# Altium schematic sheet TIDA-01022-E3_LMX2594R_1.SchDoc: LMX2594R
size 431 x 279 mm; Date: Not shown in title block; ApprovedBy: Not shown in title block; CheckedBy: Not shown in title block; Author: Not shown in title block; CompanyName: Not shown in title block; DrawnBy: Avinash N; Engineer: Not shown in title block; Organization: Not shown in title block; Address1: Not shown in title block; Address2: Not shown in title block; Address3: Not shown in title block; Address4: Not shown in title block; DocumentNumber: 1; Revision: Use project parameter SCH_Rev; SheetNumber: 10; SheetTotal: 26; PageSetup: Record=PageOptions¦CenterHorizontal=True¦CenterVertical=True¦PrintScale=1.00¦XCorrection=1.00¦YCorrection=1.00¦PrintKind=0¦BorderSize=5000000¦LeftOffset=0¦BottomOffset=0¦Orientation=2¦PaperLength=1000¦PaperWidth=1000¦Scale=100¦PaperSource=15¦PrintQuality=600¦MediaType=1¦DitherType=10¦PaperKind=Letter¦PrintScaleMode=1
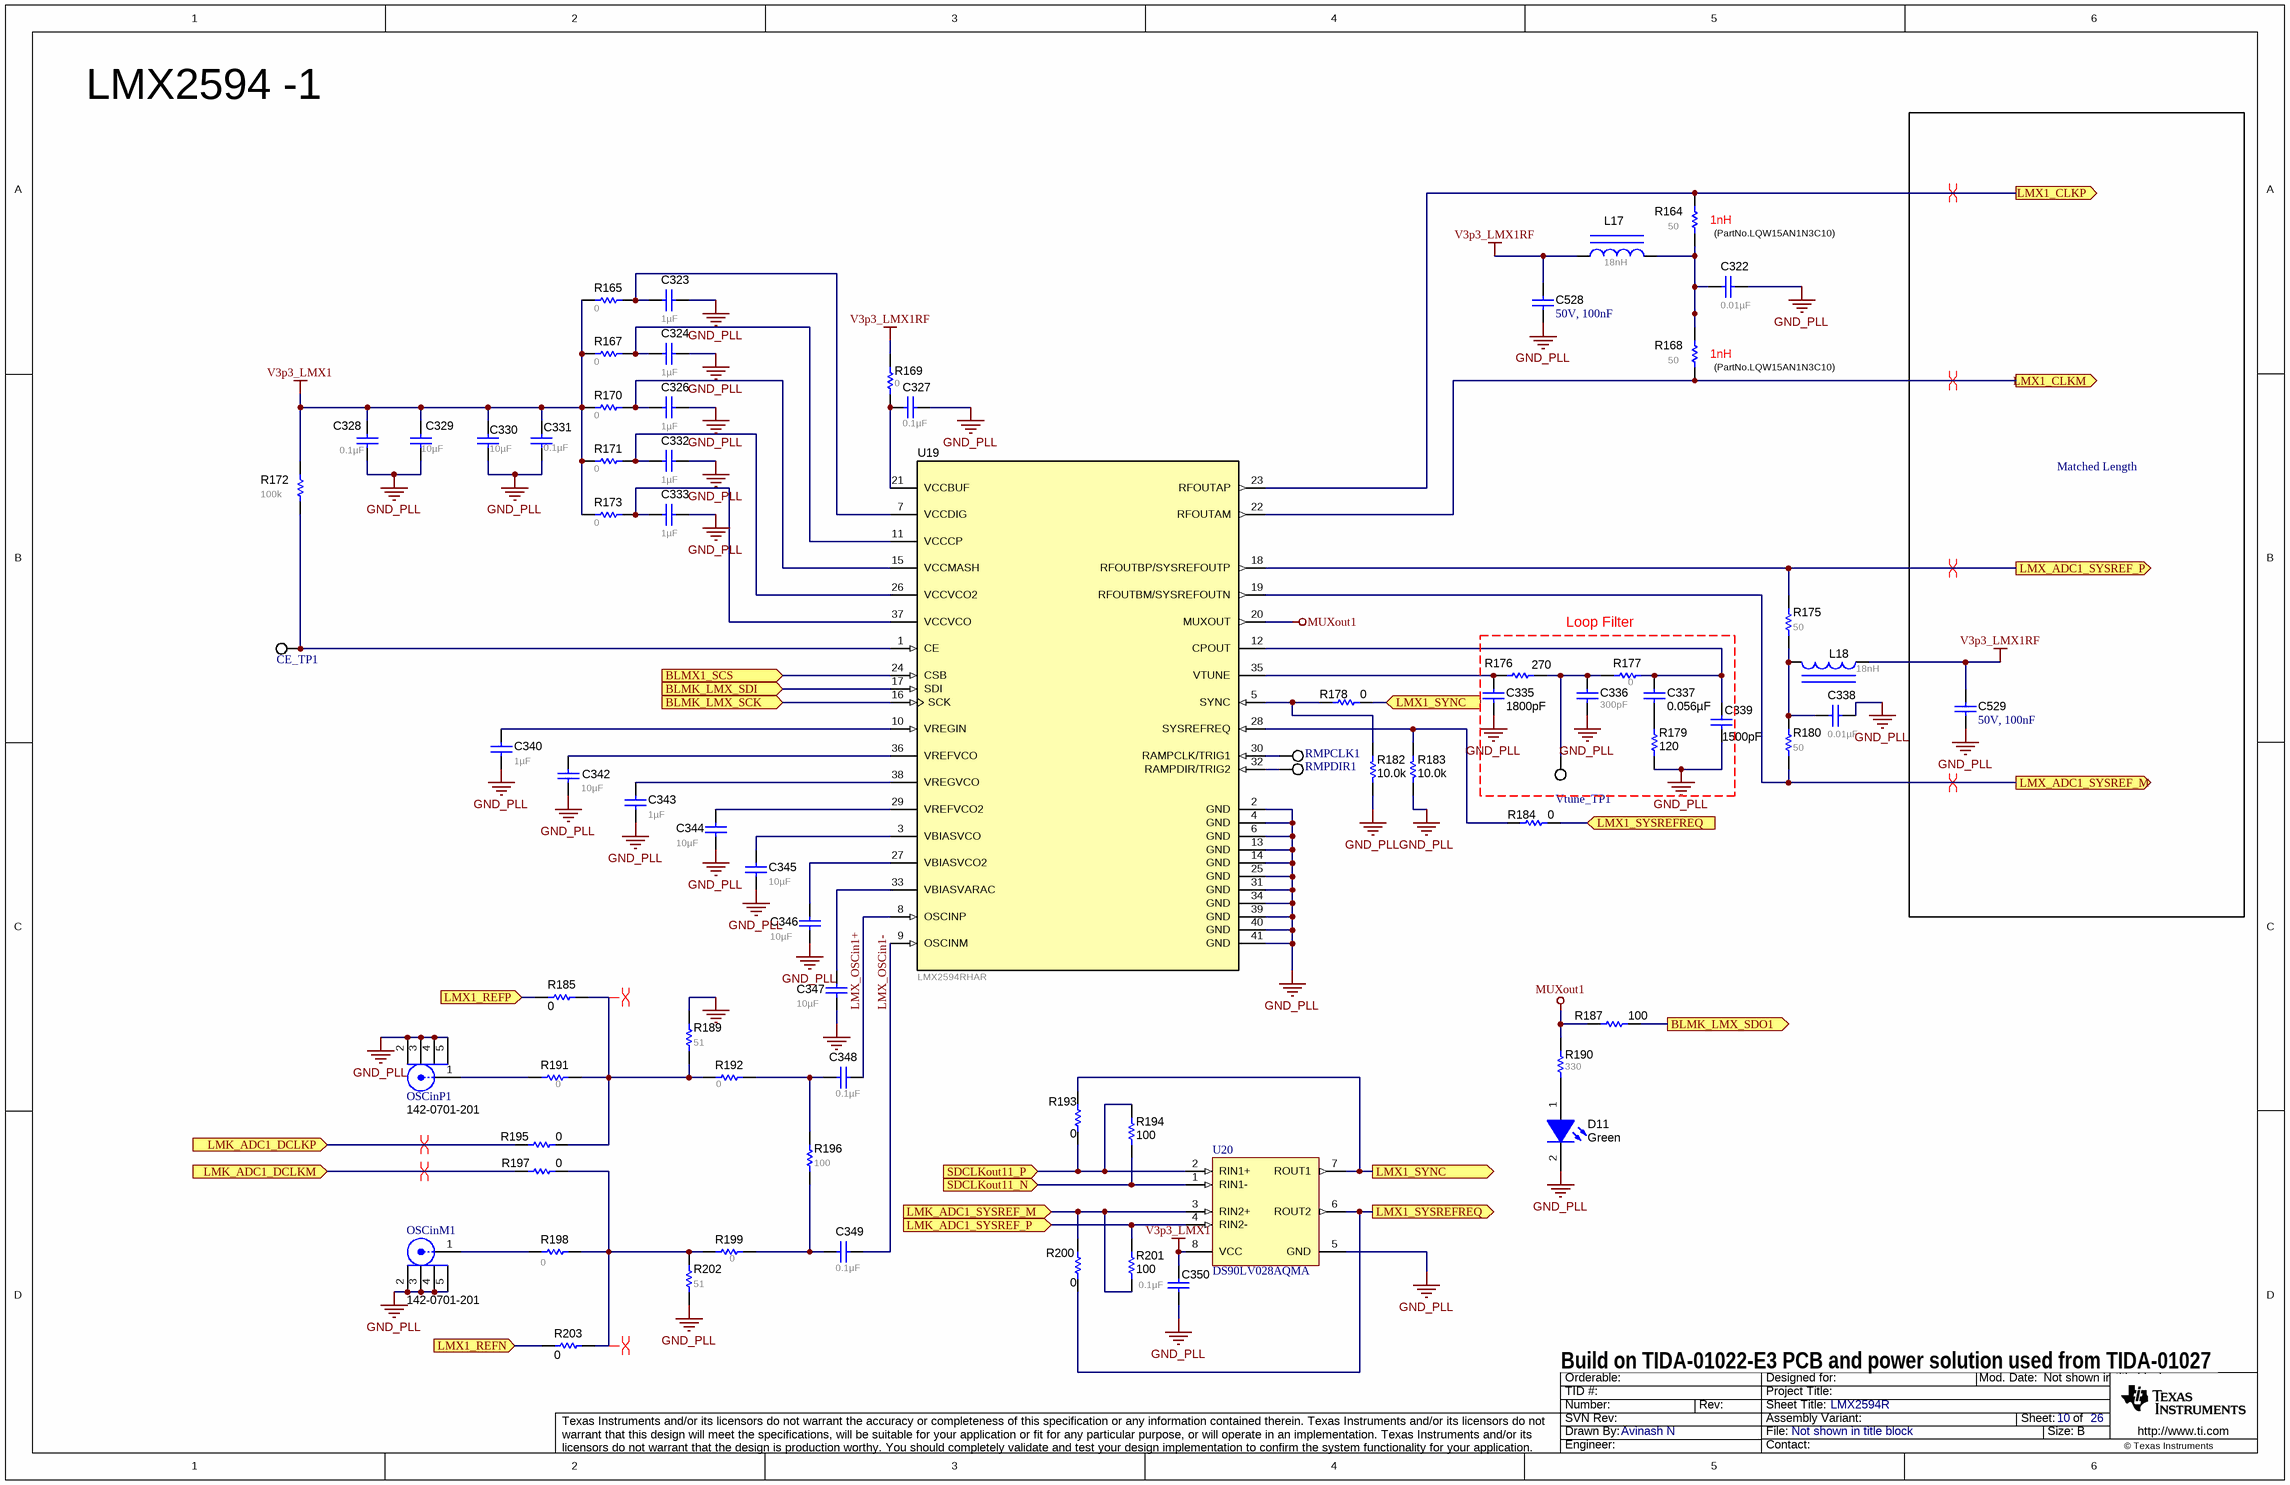
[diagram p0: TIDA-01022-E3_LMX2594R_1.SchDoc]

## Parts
C322  ValueDisplayed: 0.01µF  [0402_065]  (hidden comment: 520L103KT16T)
C323  ValueDisplayed: 1µF  [0603]  (hidden comment: C1608X7R1C105K080AC)
C324  ValueDisplayed: 1µF  [0603L]  (hidden comment: C1608X7R1C105K080AC)
C326  ValueDisplayed: 1µF  [0603L]  (hidden comment: C1608X7R1C105K080AC)
C327  ValueDisplayed: 0.1µF  [0603L]  (hidden comment: 0603YC104JAT2A)
C328  ValueDisplayed: 0.1µF  [0603]  (hidden comment: 0603YC104JAT2A)
C329  ValueDisplayed: 10µF  [0805]  (hidden comment: C0805C106K8PACTU)
C330  ValueDisplayed: 10µF  [0805]  (hidden comment: C0805C106K8PACTU)
C331  ValueDisplayed: 0.1µF  [0603]  (hidden comment: 0603YC104JAT2A)
C332  ValueDisplayed: 1µF  [0603]  (hidden comment: C1608X7R1C105K080AC)
C333  ValueDisplayed: 1µF  [0603]  (hidden comment: C1608X7R1C105K080AC)
C335  ValueDisplayed: 1800pF  [0603]  (hidden comment: GRM1885C1H182JA01D)
C336  ValueDisplayed: 300pF  [0603]  (hidden comment: GRM1885C2A301JA01D)
C337  ValueDisplayed: 0.056µF  [0603]  (hidden comment: C0603C563J4RACTU)
C338  ValueDisplayed: 0.01µF  [0402_065]  (hidden comment: 520L103KT16T)
C339  ValueDisplayed: 1500pF  [0603]  (hidden comment: 06031C152JAT2A)
C340  ValueDisplayed: 1µF  [0603]  (hidden comment: C1608X7R1C105K080AC)
C342  ValueDisplayed: 10µF  [0603]  (hidden comment: C1608X5R1A106M080AC)
C343  ValueDisplayed: 1µF  [0603]  (hidden comment: C1608X7R1C105K080AC)
C344  ValueDisplayed: 10µF  [0603]  (hidden comment: C1608X5R1A106M080AC)
C345  ValueDisplayed: 10µF  [0603]  (hidden comment: C1608X5R1A106M080AC)
C346  ValueDisplayed: 10µF  [0603]  (hidden comment: C1608X5R1A106M080AC)
C347  ValueDisplayed: 10µF  [0603]  (hidden comment: C1608X5R1A106M080AC)
C348  ValueDisplayed: 0.1µF  [0603L]  (hidden comment: 0603YC104JAT2A)
C349  ValueDisplayed: 0.1µF  [0603L]  (hidden comment: 0603YC104JAT2A)
C350  ValueDisplayed: 0.1µF  [0603]  (hidden comment: 0603YC104JAT2A)
C528  50V, 100nF  [0603_1.6x0.8x0.8mm_Reflow Soldering]
C529  50V, 100nF  [0603_1.6x0.8x0.8mm_Reflow Soldering]
CE_TP1  5002  [Keystone5002]  (value not drawn)
D11  value Green  [LTST-C191_Green]  (hidden comment: LTST-C191TGKT)
L17  ValueDisplayed: 18nH  [IND_LQG15H]  (hidden comment: LQG15HS18NJ02D)
L18  ValueDisplayed: 18nH  [IND_LQG15H]  (hidden comment: LQG15HS18NJ02D)
OSCinM1  142-0701-201  [Johnson_142-0701-20x]
OSCinP1  142-0701-201  [Johnson_142-0701-20x]
R164  ValueDisplayed: 50  [0402L]  (hidden comment: FC0402E50R0BST1)
R165  value 0  [0603]  (hidden comment: CRCW06030000Z0EA)
R167  value 0  [0603L]  (hidden comment: CRCW06030000Z0EA)
R168  ValueDisplayed: 50  [0402L]  (hidden comment: FC0402E50R0BST1)
R169  value 0  [0603L]  (hidden comment: CRCW06030000Z0EA)
R170  value 0  [0603L]  (hidden comment: CRCW06030000Z0EA)
R171  value 0  [0603]  (hidden comment: CRCW06030000Z0EA)
R172  ValueDisplayed: 100k  [0603]  (hidden comment: CRCW0603100KJNEA)
R173  value 0  [0603]  (hidden comment: CRCW06030000Z0EA)
R175  ValueDisplayed: 50  [0402L]  (hidden comment: FC0402E50R0BST1)
R176  ValueDisplayed: 270  [0603]  (hidden comment: RC0603JR-07270RL)
R177  ValueDisplayed: 0  [0603]  (hidden comment: CRCW06030000Z0EA)
R178  ValueDisplayed: 0  [0402]  (hidden comment: CRCW04020000Z0ED)
R179  ValueDisplayed: 120  [0603]  (hidden comment: RT0603DRE07120RL)
R180  ValueDisplayed: 50  [0402L]  (hidden comment: FC0402E50R0BST1)
R182  ValueDisplayed: 10.0k  [0402]  (hidden comment: CRCW040210K0DHEDP)
R183  ValueDisplayed: 10.0k  [0402]  (hidden comment: CRCW040210K0DHEDP)
R184  ValueDisplayed: 0  [0402]  (hidden comment: CRCW04020000Z0ED)
R185  ValueDisplayed: 0  [0402]  (hidden comment: CRCW04020000Z0ED)
R187  ValueDisplayed: 100  [0603]  (hidden comment: CRCW0603100RFKEA)
R189  ValueDisplayed: 51  [0603]  (hidden comment: CRCW060351R0JNEA)
R190  value 330  [0603]  (hidden comment: RC0603JR-07330RL)
R191  ValueDisplayed: 0  [0603]  (hidden comment: CRCW06030000Z0EA)
R192  ValueDisplayed: 0  [0603]  (hidden comment: CRCW06030000Z0EA)
R193  ValueDisplayed: 0  [0402]  (hidden comment: CRCW04020000Z0ED)
R194  ValueDisplayed: 100  [0402]  (hidden comment: CRCW0402100RJNED)
R195  ValueDisplayed: 0  [0402]  (hidden comment: CRCW04020000Z0ED)
R196  ValueDisplayed: 100  [0603L]  (hidden comment: CRCW0603100RFKEA)
R197  ValueDisplayed: 0  [0402]  (hidden comment: CRCW04020000Z0ED)
R198  ValueDisplayed: 0  [0603]  (hidden comment: CRCW06030000Z0EA)
R199  ValueDisplayed: 0  [0603]  (hidden comment: CRCW06030000Z0EA)
R200  ValueDisplayed: 0  [0402]  (hidden comment: CRCW04020000Z0ED)
R201  ValueDisplayed: 100  [0402]  (hidden comment: CRCW0402100RJNED)
R202  ValueDisplayed: 51  [0603]  (hidden comment: CRCW060351R0JNEA)
R203  ValueDisplayed: 0  [0402]  (hidden comment: CRCW04020000Z0ED)
RMPCLK1  5002  [Keystone5002]  (value not drawn)
RMPDIR1  5002  [Keystone5002]  (value not drawn)
U19  LMX2594RHAR  [RHA0040A]
U20  DS90LV028AQMA  [M08A_N]
Vtune_TP1  5002  [Keystone5002]  (value not drawn)

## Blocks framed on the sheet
Matched Length: C529
Loop Filter: C335-C337 C339 R176 R177 R179 Vtune_TP1

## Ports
BLMK_LMX_SCK (in), BLMK_LMX_SDI (in), BLMK_LMX_SDO1 (out), BLMX1_SCS (in), LMK_ADC1_DCLKM (in), LMK_ADC1_DCLKP (in), LMK_ADC1_SYSREF_M (in), LMK_ADC1_SYSREF_P (in), LMX1_CLKM (out), LMX1_CLKP (out), LMX1_REFN (in), LMX1_REFP (in), LMX1_SYNC (in), LMX1_SYNC (out), LMX1_SYSREFREQ (in), LMX1_SYSREFREQ (out), LMX_ADC1_SYSREF_M (out), LMX_ADC1_SYSREF_P (out), SDCLKout11_N (in), SDCLKout11_P (in)

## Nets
GND_PLL: C322.1 C323.1 C324.1 C326.2 C327.1 C328.1 C329.1 C330.1 C331.1 C332.1 C333.1 C335.1 C336.2 C338.1 C339.2 C340.1 C342.2 C343.1 C344.2 C345.2 C346.1 C347.1 C350.1 C528.2 C529.2 D11.2(K) OSCinM1.2 OSCinM1.3 OSCinM1.4 OSCinM1.5 OSCinP1.2 OSCinP1.3 OSCinP1.4 OSCinP1.5 R179.2 R182.2 R183.2 R189.2 R202.1 U19.2(GND) U19.4(GND) U19.6(GND) U19.13(GND) U19.14(GND) U19.25(GND) U19.31(GND) U19.34(GND) U19.39(GND) U19.40(GND) U19.41(GND) U20.5(GND)
MUXout1: R187.1 R190.2 U19.20(MUXOUT)
V3p3_LMX1: C328.2 C329.2 C330.2 C331.2 C350.2 R165.1 R167.1 R170.1 R171.2 R172.1 R173.2 U20.8(VCC)
V3p3_LMX1RF: C528.1 C529.1 L17.1 L18.1 R169.1
BLMK_LMX_SCK: U19.16(SCK) ; port BLMK_LMX_SCK
BLMK_LMX_SDI: U19.17(SDI) ; port BLMK_LMX_SDI
BLMK_LMX_SDO1: R187.2 ; port BLMK_LMX_SDO1
BLMX1_SCS: U19.24(CSB) ; port BLMX1_SCS
LMK_ADC1_DCLKM: R197.1 ; port LMK_ADC1_DCLKM
LMK_ADC1_DCLKP: R195.1 ; port LMK_ADC1_DCLKP
LMK_ADC1_SYSREF_M: R200.1 R201.1 U20.3(RIN2+) ; port LMK_ADC1_SYSREF_M
LMK_ADC1_SYSREF_P: R201.2 U20.4(RIN2-) ; port LMK_ADC1_SYSREF_P
LMX1_CLKM: R168.1 U19.22(RFOUTAM) ; port LMX1_CLKM
LMX1_CLKP: R164.1 U19.23(RFOUTAP) ; port LMX1_CLKP
LMX1_REFN: R203.1 ; port LMX1_REFN
LMX1_REFP: R185.2 ; port LMX1_REFP
LMX1_SYNC: R178.2 R193.1 U20.7(ROUT1) ; port LMX1_SYNC
LMX1_SYSREFREQ: R184.2 R200.2 U20.6(ROUT2) ; port LMX1_SYSREFREQ
LMX_ADC1_SYSREF_M: R180.1 U19.19(RFOUTBM/SYSREFOUTN) ; port LMX_ADC1_SYSREF_M
LMX_ADC1_SYSREF_P: R175.2 U19.18(RFOUTBP/SYSREFOUTP) ; port LMX_ADC1_SYSREF_P
LMX_OSCin1+: C348.2 U19.8(OSCINP)
LMX_OSCin1-: C349.2 U19.9(OSCINM)
SDCLKout11_N: R194.1 U20.1(RIN1-) ; port SDCLKout11_N
SDCLKout11_P: R193.2 R194.2 U20.2(RIN1+) ; port SDCLKout11_P
NetC322_2: C322.2 L17.2 R164.2 R168.2
NetC323_2: C323.2 R165.2 U19.7(VCCDIG)
NetC324_2: C324.2 R167.2 U19.11(VCCCP)
NetC326_1: C326.1 R170.2 U19.15(VCCMASH)
NetC327_2: C327.2 R169.2 U19.21(VCCBUF)
NetC332_2: C332.2 R171.1 U19.26(VCCVCO2)
NetC333_2: C333.2 R173.1 U19.37(VCCVCO)
NetC335_2: C335.2 R176.1 U19.35(VTUNE)
NetC336_1: C336.1 R176.2 R177.2 Vtune_TP1.1
NetC337_1: C337.1 C339.1 R177.1 U19.12(CPOUT)
NetC337_2: C337.2 R179.1
NetC338_2: C338.2 L18.2 R175.1 R180.2
NetC340_2: C340.2 U19.10(VREGIN)
NetC342_1: C342.1 U19.36(VREFVCO)
NetC343_2: C343.2 U19.38(VREGVCO)
NetC344_1: C344.1 U19.29(VREFVCO2)
NetC345_1: C345.1 U19.3(VBIASVCO)
NetC346_2: C346.2 U19.27(VBIASVCO2)
NetC347_2: C347.2 U19.33(VBIASVARAC)
NetC348_1: C348.1 R192.2 R196.2
NetC349_1: C349.1 R196.1 R199.1
NetCE_TP1_1: CE_TP1.1 R172.2 U19.1(CE)
NetD11_1: D11.1(A) R190.1
NetOSCinM1_1: OSCinM1.1 R198.1
NetOSCinP1_1: OSCinP1.1 R191.1
NetR178_1: R178.1 R182.1 U19.5(SYNC)
NetR183_1: R183.1 R184.1 U19.28(SYSREFREQ)
NetR185_1: R185.1 R189.1 R191.2 R192.1 R195.2
NetR197_2: R197.2 R198.2 R199.2 R202.2 R203.2
NetRMPCLK1_1: RMPCLK1.1 U19.30(RAMPCLK/TRIG1)
NetRMPDIR1_1: RMPDIR1.1 U19.32(RAMPDIR/TRIG2)

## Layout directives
differential pair: LMK_ADC1_DCLKM, LMK_ADC1_DCLKP, LMX1_CLKM, LMX1_CLKP, LMX_ADC1_SYSREF_M, LMX_ADC1_SYSREF_P, NetR185_1, NetR197_2

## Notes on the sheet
- LMX2594 -1
- (near R164) 1nH
- (near R164) (PartNo.LQW15AN1N3C10)
- (near R168) 1nH
- (near R168) (PartNo.LQW15AN1N3C10)
- Build on TIDA-01022-E3 PCB and power solution used from TIDA-01027

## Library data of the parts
C322 C338 = 520L103KT16T: CAP, CERM, 0.01 µF, 16 V, +/- 10%, X7R, 0402; Manufacturer: AT Ceramics; Polarized: N; CompType: Capacitor; Value: 0.01uF; U/M: EA; Cap_F: 0.00000001; Tolerance_%: 10; Value1: Unknown; VDC_V: 16; Value2: 16V; TaMin_C: -55; TaMax_C: 125; Cap_Case: 0402; AEC Category: Q200; SizeArea_mm2: 0.5; SizeAreaWB_mm2: 3; SizeX_mm: 1; SizeZ_mm: 0.65
C323 C332 C333 = C1608X7R1C105K080AC: CAP, CERM, 1 µF, 16 V, +/- 10%, X7R, 0603; Manufacturer: TDK; ESR_ohm: 0.0057; Polarized: N; TaMax_C: 125; TaMin_C: -55; Tolerance_%: 10; VDC_V: 16; Cap_F: 0.000001; CompType: Capacitor; Value: 1uF; Value1: 0.0057 ohm; Value2: 16V; U/M: EA; SizeArea_mm2: 1.28; SizeAreaWB_mm2: 4.68; SizeX_mm: 1.6; SizeY_mm: 0.8; SizeZ_mm: 1; AEC Category: Q200
C324 C326 = C1608X7R1C105K080AC: CAP, CERM, 1 µF, 16 V, +/- 10%, X7R, 0603; Manufacturer: TDK; Cap_Case: 0603; ESR_ohm: 0.0057; Polarized: N; TaMax_C: 125; TaMin_C: -55; Tolerance_%: 10; VDC_V: 16; Cap_F: 0.000001; CompType: Capacitor; Value: 1uF; Value1: 0.0057 ohm; Value2: 16V; U/M: EA; SizeArea_mm2: 1.28; SizeAreaWB_mm2: 4.68; SizeX_mm: 1.6; SizeY_mm: 0.8; SizeZ_mm: 1; AEC Category: Q200
C327 C348 C349 = 0603YC104JAT2A: CAP, CERM, 0.1uF, 16V, +/-5%, X7R, 0603; Manufacturer: AVX; Cap_Case: 0603; ESR_Ohm: 0.039; Polarized: N; TaMax_C: 125; TaMin_C: -55; Tolerance_%: 5; VDC_V: 16; Cap_F: 0.0000001; CompType: Capacitor; Value1: 0.039 ohm; U/M: EA
C328 C331 C350 = 0603YC104JAT2A: CAP, CERM, 0.1uF, 16V, +/-5%, X7R, 0603; Manufacturer: AVX; ESR_Ohm: 0.039; Polarized: N; TaMax_C: 125; TaMin_C: -55; Tolerance_%: 5; VDC_V: 16; Cap_F: 0.0000001; CompType: Capacitor; Value1: 0.039 ohm; U/M: EA
C329 C330 = C0805C106K8PACTU: CAP, CERM, 10uF, 10V, +/-10%, X5R, 0805; Manufacturer: Kemet; ESR_Ohm: 0.003; IRMS_A: 11.43; Polarized: N; TaMax_C: 85; TaMin_C: -55; Tolerance_%: 10; Cap_F: 0.00001; CompType: Capacitor; U/M: EA; Value1: 0.003 ohm
C335 = GRM1885C1H182JA01D: CAP, CERM, 1800 pF, 50 V, +/- 5%, C0G/NP0, 0603; Manufacturer: MuRata; Polarized: N; TaMax_C: 125; TaMin_C: -55; Tolerance_%: 5; VDC_V: 50; Cap_F: 0.0000000018; CompType: Capacitor; Value: 1800pF; Value1: Unknown; Value2: 50V; U/M: EA; SizeArea_mm2: 1.28; SizeAreaWB_mm2: 4.68; SizeX_mm: 1.6; SizeY_mm: 0.8; SizeZ_mm: 1; AEC Category: Q200
C336 = GRM1885C2A301JA01D: CAP, CERM, 300pF, 100V, +/-5%, C0G/NP0, 0603; Manufacturer: MuRata; Polarized: N; TaMax_C: 125; TaMin_C: -55; Tolerance_%: 5; VDC_V: 100; Cap_F: 0.0000000003; CompType: Capacitor; Value1: Unknown; U/M: EA
C337 = C0603C563J4RACTU: CAP, CERM, 0.056 µF, 16 V, +/- 5%, X7R, 0603; Manufacturer: Kemet; Polarized: N; TaMax_C: 125; TaMin_C: -55; Tolerance_%: 5; VDC_V: 16; Cap_F: 0.000000056; CompType: Capacitor; Value: 0.056uF; Value1: Unknown; Value2: 16V; U/M: EA; AEC Category: Q200; SizeArea_mm2: 1.28; SizeAreaWB_mm2: 4.68; SizeX_mm: 1.6; SizeY_mm: 0.8; SizeZ_mm: 1
C339 = 06031C152JAT2A: CAP, CERM, 1500 pF, 100 V, +/- 5%, X7R, 0603; Manufacturer: AVX; ESR_ohm: 0.229; Polarized: N; TaMax_C: 125; TaMin_C: -55; Tolerance_%: 5; VDC_V: 100; Cap_F: 0.0000000015; CompType: Capacitor; Value: 1500pF; Value1: 0.229 ohm; Value2: 100V; U/M: EA; AEC Category: Q200; SizeArea_mm2: 1.28; SizeAreaWB_mm2: 4.68; SizeX_mm: 1.6; SizeY_mm: 0.8; SizeZ_mm: 1
C340 = C1608X7R1C105K080AC: CAP, CERM, 1 µF, 16 V, +/- 10%, X7R, 0603; Manufacturer: TDK; Polarized: N; CompType: Capacitor; Value: 1uF; U/M: EA; Cap_F: 0.000001; Tolerance_%: 10; ESR_ohm: 0.0057; Value1: 0.0057 ohm; VDC_V: 16; Value2: 16V; TaMin_C: -55; TaMax_C: 125; AEC Category: Q200
C342 C344-C347 = C1608X5R1A106M080AC: CAP, CERM, 10 µF, 10 V, +/- 20%, X5R, 0603; Manufacturer: TDK; ESR_ohm: 0.0078; IRMS_A: 1.85; Polarized: N; TaMax_C: 85; TaMin_C: -55; Tolerance_%: 20; VDC_V: 10; Cap_F: 0.00001; CompType: Capacitor; Value: 10uF; U/M: EA; Value1: 0.0078 ohm; Value2: 10V; AEC Category: Q200
C343 = C1608X7R1C105K080AC: CAP, CERM, 1 µF, 16 V, +/- 10%, X7R, 0603; Manufacturer: TDK; ESR_ohm: 0.0057; Polarized: N; TaMax_C: 125; TaMin_C: -55; Tolerance_%: 10; VDC_V: 16; Cap_F: 0.000001; CompType: Capacitor; Value: 1uF; U/M: EA; Value1: 0.0057 ohm; Value2: 16V; AEC Category: Q200
C528 C529 = 885012206095: WCAP-CSGP Ceramic Capacitors, 0603, X7R, 50V, 100nF; Rated Voltage: 50V DC
CE_TP1 RMPCLK1 RMPDIR1 Vtune_TP1 = 5002: Test Point, Miniature, White, TH; Manufacturer: Keystone; CompType: Test Point Loop; ContactFinish: Silver; Green_Lifecycle: Active; Green_REACh: Passed
D11 = LTST-C191TGKT: LED, Green, SMD; Manufacturer: Lite-On; Type: InGaN; Vf_V: 3.2; Value2: 3.2V; Io_A: 0.02; Value1: W; U/M: EA
L17 L18 = LQG15HS18NJ02D: Inductor, Multilayer, Air Core, 18 nH, 0.3 A, 0.36 ohm, SMD; Manufacturer: MuRata; Value: 18nH; Ind_H: 18.0E-9; Imax_A: 0.3; Irms: 0.3A @ C rise; Isat: 0.3A @ % inductance drop; DCR_ohm: 0.36; Value2: 0.3A; AEC Category: Q200
OSCinM1 OSCinP1 = 142-0701-201: Connector, TH, SMA; Manufacturer: Emerson Network Power; SymbolCreator: X0208326
R164 R168 R175 R180 = FC0402E50R0BST1: RES, 50, 0.1%, 0.05 W, 0402; Manufacturer: Vishay-Dale; CompType: Resistor; Value: 50; Value_Code: 50R0; Tolerance_%: 0.1; Power_W: 0.05; Value2: 0.05W; TempCo: 25 ppm/C; U/M: EA; SizeArea_mm2: 0.5; SizeX_mm: 1; SizeZ_mm: 0.6; AEC Category: Q200; AEC Qualified: N
R165 R167 R169-R171 R173 = CRCW06030000Z0EA: RES, 0 ohm, 5%, 0.1W, 0603; Manufacturer: Vishay-Dale; CompType: Resistor; Tolerance_%: 5; VDC_V: 75; Power_W: 0.1; U/M: EA; Value_Code: 0000; EIA_Code: E24
R172 = CRCW0603100KJNEA: RES, 100 k, 5%, 0.1 W, 0603; Manufacturer: Vishay-Dale; CompType: Resistor; Tolerance_%: 5; VDC_V: 75; Power_W: 0.1; Res_ohm: 100000; Value: 100k; U/M: EA; Value2: 0.1W; EIA_Code: E24; TempCo: 200 ppm/C; SizeArea_mm2: 1.28; SizeX_mm: 1.6; SizeY_mm: 0.8; SizeZ_mm: 1; AEC Category: Q200
R176 = RC0603JR-07270RL: RES, 270, 5%, 0.1 W, 0603; Manufacturer: Yageo America; CompType: Resistor; Tolerance_%: 5; VDC_V: 50; Power_W: 0.1; Value: 270; U/M: EA; Value_Code: 270R; Value2: 0.1W; EIA_Code: E24; TempCo: 100 ppm/C; SizeArea_mm2: 1.28; SizeX_mm: 1.6; SizeY_mm: 0.8; SizeZ_mm: 1; AEC Category: Q200
R177 R191 R192 R198 R199 = CRCW06030000Z0EA: RES, 0, 5%, 0.1 W, 0603; Manufacturer: Vishay-Dale; CompType: Resistor; Tolerance_%: 5; VDC_V: 75; Power_W: 0.1; Value: 0; U/M: EA; Value_Code: 0000; Value2: 0.1W; EIA_Code: E24; TempCo: 200 ppm/C; SizeArea_mm2: 1.28; SizeX_mm: 1.6; SizeY_mm: 0.8; SizeZ_mm: 1; AEC Category: Q200
R178 R184 R193 R195 R197 R200 = CRCW04020000Z0ED: RES, 0, 5%, 0.063 W, 0402; Manufacturer: Vishay-Dale; CompType: Resistor; Value: 0; Value_Code: 0000; Tolerance_%: 5; Power_W: 0.063; Value2: 0.063W; VDC_V: 50; TempCo: 200 ppm/C; SizeArea_mm2: 0.5; SizeX_mm: 1; SizeZ_mm: 0.6; EIA_Code: E24; U/M: EA; AEC Category: Q200
R179 = RT0603DRE07120RL: RES, 120, 0.5%, 0.1 W, 0603; Manufacturer: Yageo America; CompType: Resistor; Tolerance_%: 0.5; VDC_V: 75; Power_W: 0.1; Value: 120; U/M: EA; Value_Code: 120R; Value2: 0.1W; TempCo: 50 ppm/C; EIA_Code: E192; SizeArea_mm2: 1.28; SizeX_mm: 1.6; SizeY_mm: 0.8; SizeZ_mm: 1; AEC Category: Q200
R182 R183 = CRCW040210K0DHEDP: RES, 10.0 k, 0.5%, 0.063 W, 0402; Manufacturer: Vishay-Dale; CompType: Resistor; Value: 10.0k; Res_ohm: 10000; Value_Code: 10k0; Tolerance_%: 0.5; Power_W: 0.063; Value2: 0.063W; VDC_V: 50; TempCo: 50 ppm/C; SizeX_mm: 1; SizeZ_mm: 0.6; EIA_Code: E192; U/M: EA; AEC Category: Q200
R185 R203 = CRCW04020000Z0ED: RES, 0, 5%, 0.063 W, 0402; Manufacturer: Vishay-Dale; CompType: Resistor; Tolerance_%: 5; VDC_V: 50; Power_W: 0.063; Value: 0; U/M: EA; Value_Code: 0000; Value2: 0.063W; EIA_Code: E24; TempCo: 200 ppm/C; SizeArea_mm2: 0.5; SizeX_mm: 1; SizeZ_mm: 0.6; AEC Category: Q200
R187 = CRCW0603100RFKEA: RES, 100, 1%, 0.1 W, 0603; Manufacturer: Vishay-Dale; CompType: Resistor; Value: 100; Value_Code: 100R; Tolerance_%: 1; Power_W: 0.1; Value2: 0.1W; VDC_V: 75; TempCo: 100 ppm/C; SizeArea_mm2: 1.28; SizeX_mm: 1.6; SizeY_mm: 0.8; EIA_Code: E96; U/M: EA; AEC Category: Q200
R189 R202 = CRCW060351R0JNEA: RES, 51, 5%, 0.1 W, 0603; Manufacturer: Vishay-Dale; CompType: Resistor; Value: 51; Value_Code: 51R0; Tolerance_%: 5; Power_W: 0.1; Value2: 0.1W; VDC_V: 75; TempCo: 200 ppm/C; EIA_Code: E24; U/M: EA; SizeArea_mm2: 1.28; SizeX_mm: 1.6; SizeY_mm: 0.8; SizeZ_mm: 1; AEC Category: Q200
R190 = RC0603JR-07330RL: RES, 330 ohm, 5%, 0.1W, 0603; Manufacturer: Yageo America; CompType: Resistor; Tolerance_%: 5; VDC_V: 50; Power_W: 0.1; U/M: EA; Value_Code: 330R; EIA_Code: E24
R194 R201 = CRCW0402100RJNED: RES, 100, 5%, 0.063 W, 0402; Manufacturer: Vishay-Dale; CompType: Resistor; Value: 100; Value_Code: 100R; Tolerance_%: 5; Power_W: 0.063; Value2: 0.063W; VDC_V: 50; TempCo: 200 ppm/C; SizeArea_mm2: 0.5; SizeX_mm: 1; SizeZ_mm: 0.6; EIA_Code: E24; U/M: EA; AEC Category: Q200
R196 = CRCW0603100RFKEA: RES, 100, 1%, 0.1 W, 0603; Manufacturer: Vishay-Dale; CompType: Resistor; Tolerance_%: 1; VDC_V: 75; Power_W: 0.1; Value: 100; U/M: EA; Value_Code: 100R; Value2: 0.1W; EIA_Code: E96; TempCo: 100 ppm/C; SizeArea_mm2: 1.28; SizeX_mm: 1.6; SizeY_mm: 0.8; AEC Category: Q200
U19 = LMX2594RHAR: High Performance, Wideband PLLatinum RF Synthesizer, RHA0040A (VQFN-40); Alternate PartNumber: LMX2594RHAT; Manufacturer: Texas Instruments; SymbolCreator: Altium; SizeArea_mm2: 36; SizeAreaWB_mm2: 64; SizeX_mm: 6; SizeZ_mm: 1; CompType: IC; U/M: EA
U20 = DS90LV028AQMA: Automotive LVDS Dual Differential Line Receiver, 8-pin Narrow SOIC; Manufacturer: Texas Instruments; PackageTopMarking: NSZXTT*90LV0*28AQM; PowerWise: N; CompType: Interface IC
